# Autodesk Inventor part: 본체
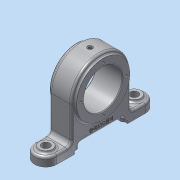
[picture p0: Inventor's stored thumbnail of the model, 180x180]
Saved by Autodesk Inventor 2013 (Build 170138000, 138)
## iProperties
Created: 2019-05
Part Number: 본체
Material: 알루미늄 6061
Document SubType Name: Modeling
Designer: dg
Density: 2.71 g/cm^3
Mass: 456.712 g
Surface Area: 318.708 cm^2
Volume: 168.528 cm^3
Author: dg
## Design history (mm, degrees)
sketch "스케치1"
  geometry: L1 (18, 0)-(-18, 0); L2 (-18, 0)-(-18, 36); L3 (-18, 36)-(-15, 36); L4 (-15, 36)-(-15, 40); L5 (-15, 40)-(15, 40); L6 (15, 40)-(15, 36); L7 (15, 36)-(18, 36); L8 (18, 36)-(18, 0); L9 (18, 26)-(-18, 26); 2 further points
  constraints: 18 end point, 4 parallel, 3 perpendicular, 2 point on line, 1 coincident, 1 collinear, 1 horizontal, 1 midpoint
  dimensions: "d0" = 36 distance of L1.start L1.end; "d5" = 72 diameter of L3 L1; "d6" = 72 diameter of L7 L1; "d7" = 80 diameter of L5 L1; "d8" = 52 diameter of L9 L1; "d10" = 15 distance from line of point (0, 0) L6; "d11" = 15 distance from line of point (0, 0) L4
revolve "회전1" sketch "스케치1" stored, may be unused: angle "d12" = 90 deg
node "작업 평면1"
sketch "스케치2"
  geometry: L1 (-15, 60)-(15, 60); L2 (15, 60)-(15, -60); L3 (15, -60)-(-15, -60); L4 (-15, -60)-(-15, 60); A1 r 15 centre (0, -60) between (-15, -60) and (15, -60); A2 r 15 centre (0, 60) between (15, 60) and (-15, 60); 3 further points
  constraints: 8 end point, 4 point on circle, 4 tangent, 2 centre point, 2 midpoint, 2 parallel, 1 horizontal, 1 horizontal alignment, 1 perpendicular, 1 vertical alignment
  dimensions: "d14" = 30 distance of L2.end L3.end; "d15" = 120 distance of L1.end L2.end
extrude "돌출2" join sketch "스케치2" distance "d18" = 12; taper "d19" = 0 deg
sketch "스케치3"
  geometry: L1 (-4, 24)-(0, 24); L2 (0, 24)-(0, 96); L3 (0, 96)-(-4, 96); L4 (-4, 96)-(-4, 24); 3 further points
  constraints: 8 end point, 2 parallel, 1 horizontal, 1 horizontal alignment, 1 midpoint, 1 perpendicular, 1 vertical alignment
  dimensions: "d20" = 4 distance of L3.end L2.end; "d21" = 72 distance of L2.end L1.end
extrude "돌출3" cut sketch "스케치3" stored distance "d22" = 0; taper "d23" = 0 deg
sketch "스케치4"
  geometry: L1 (2, 30)-(8, 30); L2 (8, 30)-(8, 90); L3 (8, 90)-(2, 90); L4 (2, 90)-(2, 30); 3 further points
  constraints: 8 end point, 2 parallel, 1 horizontal, 1 horizontal alignment, 1 midpoint, 1 perpendicular, 1 vertical alignment
  dimensions: "d24" = 6 distance of L3.end L2.end; "d25" = 60 distance of L2.end L1.end
extrude "돌출4" cut sketch "스케치4" stored distance "d26" = 12; taper "d27" = 0 deg
sketch "스케치5"
  geometry: L1 (-15, 40)-(15, 40); L2 (15, 40)-(15, -40); L3 (15, -40)-(-15, -40); L4 (-15, -40)-(-15, 40); 3 further points
  constraints: 8 end point, 2 midpoint, 2 parallel, 1 horizontal, 1 horizontal alignment, 1 perpendicular, 1 vertical alignment
  dimensions: "d28" = 30 distance of L2.end L3.end; "d29" = 80 distance of L1.end L2.end
extrude "돌출5" join sketch "스케치5" stored distance "d30" = 12; taper "d31" = 0 deg
sketch "스케치6"
  geometry: C1 r 9 at (0, 60); C2 r 9 at (0, -60); A1 r 15 centre (0, -60) between (-15, -60) and (15, -60) reference; A2 r 15 centre (0, 60) between (15, 60) and (-15, 60) reference; 1 further point
  constraints: 2 centre point, 2 coincident
  dimensions: "d32" = 18 diameter of C1; "d33" = 18 diameter of C2
extrude "돌출6" join sketch "스케치6" distance "d34" = 3; taper "d35" = 0 deg
sketch "스케치7"
  geometry: C1 r 9 at (0, 0) reference; C2 r 9 at (0, 120) reference; 1 further point
hole "구멍1" sketch "스케치7" at (0, 0), (0, 120) diameter "d36" = 11; stored, may be unused: countersink angle "d40" = 90 deg, drill point angle "d42" = 118 deg; dims "d37" = 6, "d38" = 4, "d39" = 2, "d41" = 8
sketch "스케치8"
  geometry: C1 r 36 at (0, 0) reference; 1 further point
  constraints: 1 vertical alignment
  dimensions: "d43" = 31 distance of C1.centre point (0, 31)
hole "구멍2" sketch "스케치8" at (0, 31) diameter "d44" = 3.242; stored, may be unused: countersink angle "d48" = 90 deg, drill point angle "d50" = 118 deg; dims "d45" = 6, "d46" = 4, "d47" = 2, "d49" = 8
node "작업 평면2"
sketch "스케치9"
  geometry: C1 r 3.5 at (0, 0); 1 further point
  constraints: 1 centre point, 1 coincident
  dimensions: "d55" = 7 diameter of C1
extrude "돌출7" cut sketch "스케치9" distance "d56" = 1; taper "d57" = 0 deg
sketch "스케치10"
  geometry: C1 r 3.5 at (0, 0) reference
hole "구멍3" sketch "스케치10" at (0, 0) diameter "d58" = 4.917; stored, may be unused: countersink angle "d62" = 90 deg, drill point angle "d64" = 118 deg; dims "d59" = 7, "d60" = 4, "d61" = 2, "d63" = 9
fillet "모깎기1" dims "d65" = 6
fillet "모깎기2" dims "d66" = 3
fillet "모깎기3" dims "d67" = 3
fillet "모깎기4" dims "d68" = 3
chamfer "모따기1" distance "d69" = 1; stored, may be unused: second distance "d70" = 2, angle "d71" = 45 deg
sketch "스케치12"
  geometry: C1 r 1.5 at (-26, 0); 1 further point
  constraints: 1 centre point, 1 horizontal alignment, 1 other
  dimensions: "d72" = 3 diameter of C1
extrude "돌출8" cut sketch "스케치12" stored distance "d73" = 1; taper "d74" = 0 deg
sketch "스케치13"
  geometry: L1 (-10, 33)-(-10, 87) reference; A1 r 39 centre (-60, 60) between (-47.671, 23) and (-47.671, 97) reference; 1 further point
  constraints: 1 horizontal alignment, 1 other
  dimensions: "d75" = 7 distance from line of L1 point (-17, 60)
feature "엠보싱1" sketch "스케치13" dims "d0" = 36, "d5" = 72, "d6" = 72, "d7" = 80, "d8" = 52, "d10" = 15, "d11" = 15, "d18" = 12, "d76" = 0.5, "d77" = 0
sketch "스케치15"
  geometry: C1 r 3.5 at (0, 0) reference; C2 r 1 at (0, 0)
  constraints: 1 centre point, 1 coincident
  dimensions: "d81" = 2 diameter of C2
extrude "돌출10" cut sketch "스케치15" stored distance "d82" = 10; taper "d83" = 0 deg
node "솔리드1"
pattern_circular "원형 패턴1" dims angle "d52" = 360 deg
mirror "대칭1"
